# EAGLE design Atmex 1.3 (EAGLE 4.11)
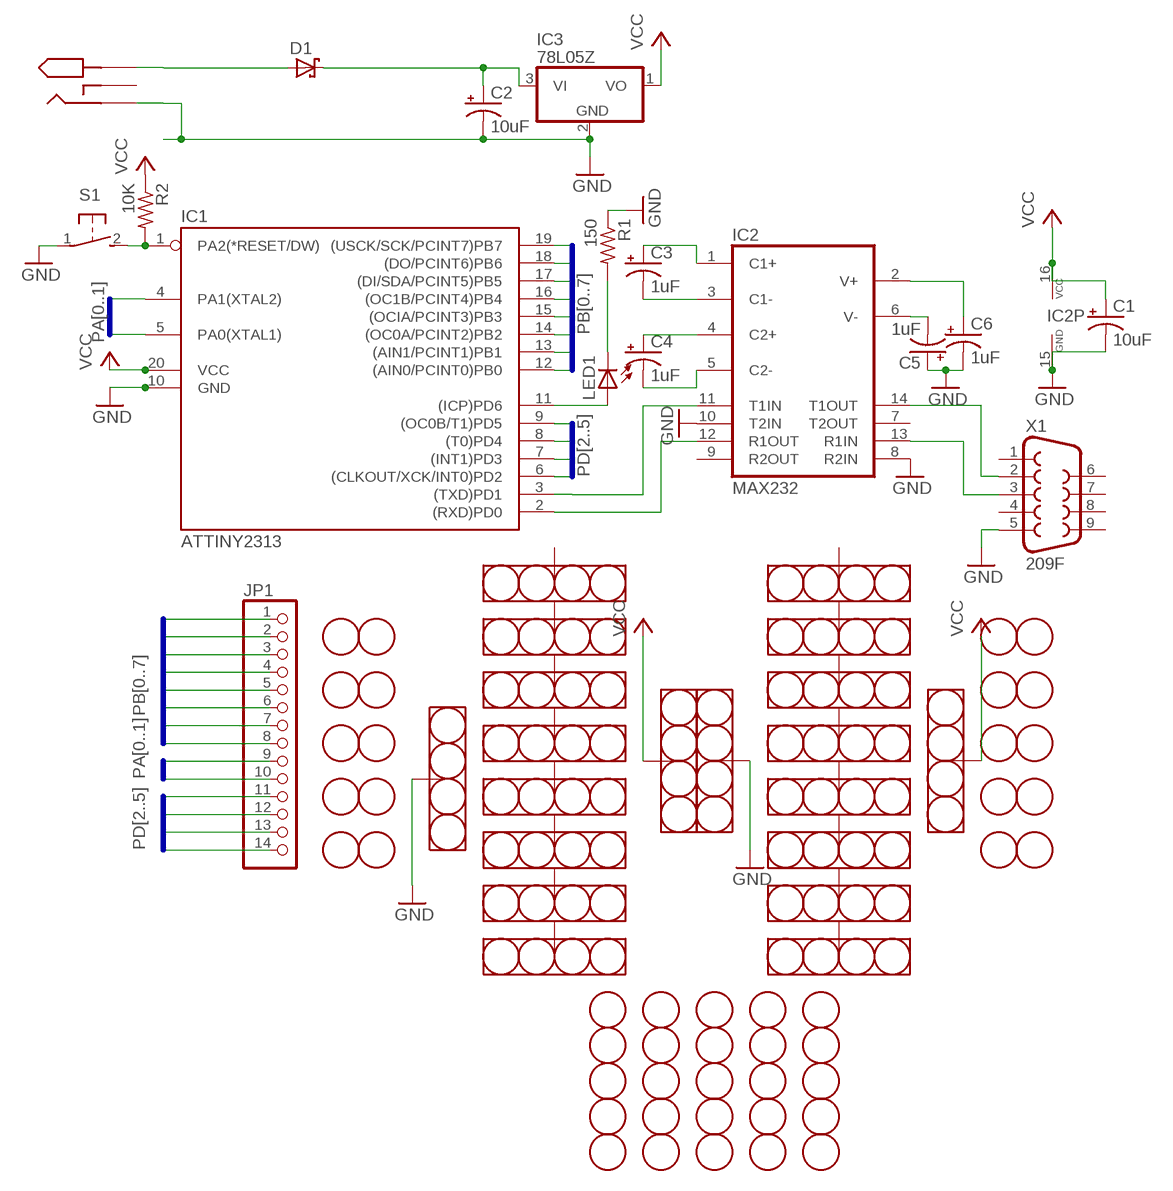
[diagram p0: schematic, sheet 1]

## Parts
C1  10uF  CPOL-USE2-5  [E2-5]
C2  10uF  CPOL-USE2-5  [E2-5]
C3  1uF  CPOL-USE1.8-4  [E1,8-4]
C4  1uF  CPOL-USE1.8-4  [E1,8-4]
C5  1uF  CPOL-USE1.8-4  [E1,8-4]
C6  1uF  CPOL-USE1.8-4  [E1,8-4]
D1  SCHOTTKY-DIODEDO35-7  [DO35-7]
IC1  ATTINY2313  [DIL20]
IC2  MAX232  [DIL16]
IC3  78L05Z  [TO92]
JP1  PINHD-1X14  [1X14]
LED1  LED5MM  [LED5MM]
R1  150  R-US_0204/7  [0204/7]
R2  10K  R-US_0204/7  [0204/7]
S1  31-XX  [B3F-31XX]
U$1  2.1MMJACK  [PJ-102A]
U$2  PROTOAREAPROTO3  PROTOAREA3  [PROTO_3]
U$3  PROTOAREAPROTO3  PROTOAREA3  [PROTO_3]
U$4  PROTOAREAPROTO3  PROTOAREA3  [PROTO_3]
U$5  PROTOAREAPROTO3  PROTOAREA3  [PROTO_3]
U$6  PROTOAREAPROTO3  PROTOAREA3  [PROTO_3]
U$7  PROTOAREAPROTO3  PROTOAREA3  [PROTO_3]
U$8  PROTOAREAPROTO3  PROTOAREA3  [PROTO_3]
U$9  PROTOAREAPROTO3  PROTOAREA3  [PROTO_3]
U$10  PROTOAREAPROTO3  PROTOAREA3  [PROTO_3]
U$11  PROTOAREAPROTO3  PROTOAREA3  [PROTO_3]
U$12  HEADER12  [HEADER_12]
U$13  HEADER12  [HEADER_12]
U$14  PROTOAREAPROTO3  PROTOAREA3  [PROTO_3]
U$15  PROTOAREAPROTO3  PROTOAREA3  [PROTO_3]
U$16  PROTOAREA  PROTOAREA12  [PROTO_12]
U$17  PROTOAREA  PROTOAREA12  [PROTO_12]
U$18  PROTOAREAPROTO3  PROTOAREA3  [PROTO_3]
U$19  PROTOAREAPROTO3  PROTOAREA3  [PROTO_3]
U$21  PROTOAREAPROTO8  PROTOAREA8  [PROTO_8]
U$22  PROTOAREAPROTO8  PROTOAREA8  [PROTO_8]
U$23  PROTOAREAPROTO3  PROTOAREA3  [PROTO_3]
U$24  PROTOAREAPROTO3  PROTOAREA3  [PROTO_3]
U$25  HEADER12  [HEADER_12]
U$26  HEADER12  [HEADER_12]
U$27  HEADER14  [HEADER_14]
U$28  HEADER8  [HEADER_8]
U$29  HEADER8  [HEADER_8]
U$30  HEADER8  [HEADER_8]
U$31  HEADER8  [HEADER_8]
X1  209F  F09D  [F09D]

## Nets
GND: C1.- C2.- C5.+ C6.- IC1.10(GND) IC2.8(R2IN) IC2.10(T2IN) IC2.15(GND) IC3.2(GND) R1.1 S1.1(P) U$1.R U$16.P$1 U$22.P$1 X1.5
N$1: C3.- IC2.3(C1-)
N$2: C3.+ IC2.1(C1+)
N$3: C4.+ IC2.4(C2+)
N$4: C4.- IC2.5(C2-)
N$5: IC1.1(PA2(*RESET/DW)) R2.2 S1.2(S)
N$6: C2.+ D1.C IC3.3(VI)
N$7: C5.- IC2.6(V-)
N$8: IC2.13(R1IN) X1.3
N$9: C6.+ IC2.2(V+)
N$10: IC2.14(T1OUT) X1.2
N$11: IC1.11((ICP)PD6) LED1.A
N$12: LED1.K(C) R1.2
N$13: D1.A U$1.T
PA0: IC1.5(PA0(XTAL1)) JP1.9
PA1: IC1.4(PA1(XTAL2)) JP1.10
PB0: IC1.12((AIN0/PCINT0)PB0) JP1.1
PB1: IC1.13((AIN1/PCINT1)PB1) JP1.2
PB2: IC1.14((OC0A/PCINT2)PB2) JP1.3
PB3: IC1.15((OCIA/PCINT3)PB3) JP1.4
PB4: IC1.16((OC1B/PCINT4)PB4) JP1.5
PB5: IC1.17((DI/SDA/PCINT5)PB5) JP1.6
PB6: IC1.18((DO/PCINT6)PB6) JP1.7
PB7: IC1.19((USCK/SCK/PCINT7)PB7) JP1.8
PD0: IC1.2((RXD)PD0) IC2.12(R1OUT)
PD1: IC1.3((TXD)PD1) IC2.11(T1IN)
PD2: IC1.6((CLKOUT/XCK/INT0)PD2) JP1.11
PD3: IC1.7((INT1)PD3) JP1.12
PD4: IC1.8((T0)PD4) JP1.13
PD5: IC1.9((OC0B/T1)PD5) JP1.14
VCC: C1.+ IC1.20(VCC) IC2.16(VCC) IC3.1(VO) R2.1 U$17.P$1 U$21.P$1
Unconnected: IC2.7(T2OUT) IC2.9(R2OUT) U$1.T_S U$2.P$1 U$3.P$1 U$4.P$1 U$5.P$1 U$6.P$1 U$7.P$1 U$8.P$1 U$9.P$1 U$10.P$1 U$11.P$1 U$14.P$1 U$15.P$1 U$18.P$1 U$19.P$1 U$23.P$1 U$24.P$1 X1.1 X1.4 X1.6 X1.7 X1.8 X1.9

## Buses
PB[0..7]
PD[2..5]
PA[0..1]

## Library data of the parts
C1-C6 = rcl:CPOL-US: POLARIZED CAPACITOR, American symbol
D1 = diode:SCHOTTKY-DIODE: Schottky Diode
IC1 = atmex:ATTINY2313
IC2 = maxim:MAX232: RS232 TRANSEIVER
IC3 = linear:78*: Positive VOLTAGE REGULATOR
JP1 = pinhead:PINHD-1X14: PIN HEADER
LED1 = led:LED: LED
R1 R2 = rcl:R-US_: RESISTOR, American symbol
S1 = switch-omron:31-XX: OMRON SWITCH
U$1 = atmex:2.1MMJACK
U$2-U$11 U$14-U$19 U$21-U$24 = atmex:PROTOAREA
U$12 U$13 U$25-U$31 = atmex:HEADER
X1 = con-subd:F09: SUB-D

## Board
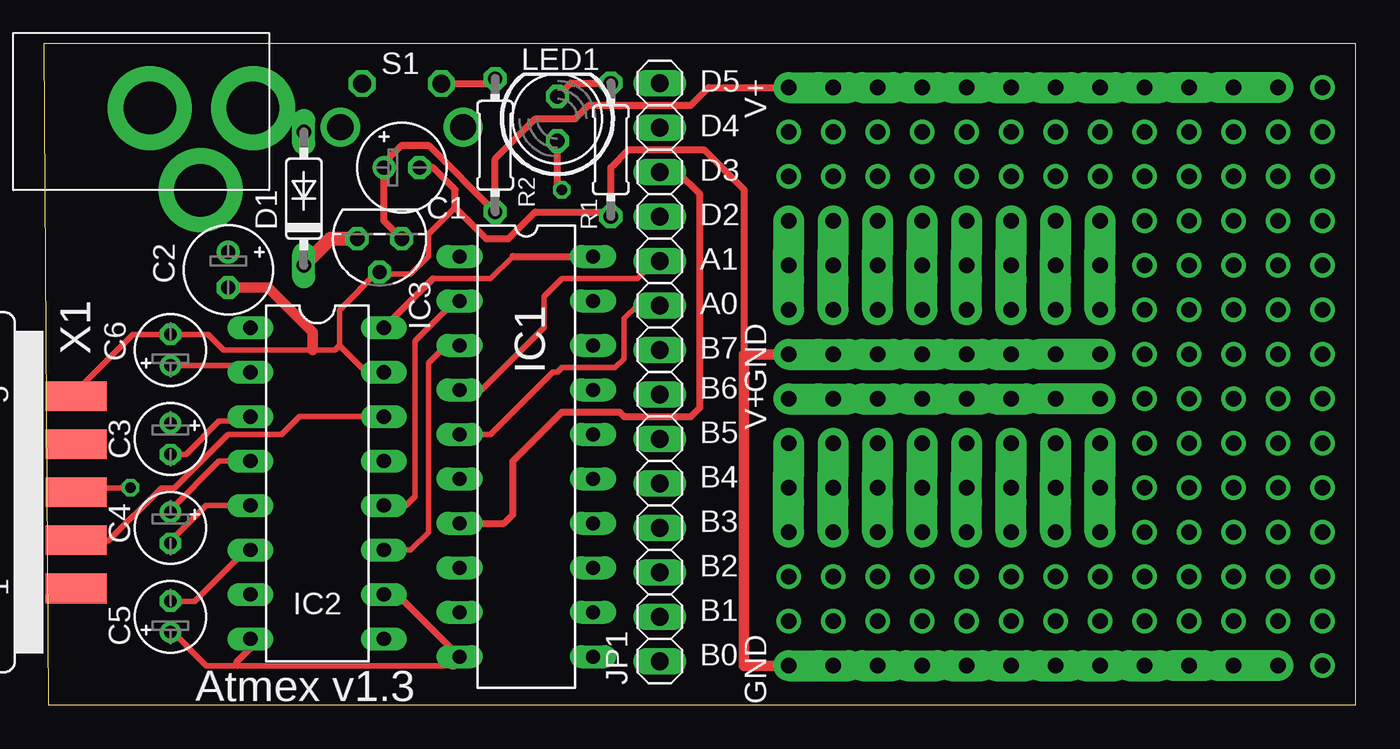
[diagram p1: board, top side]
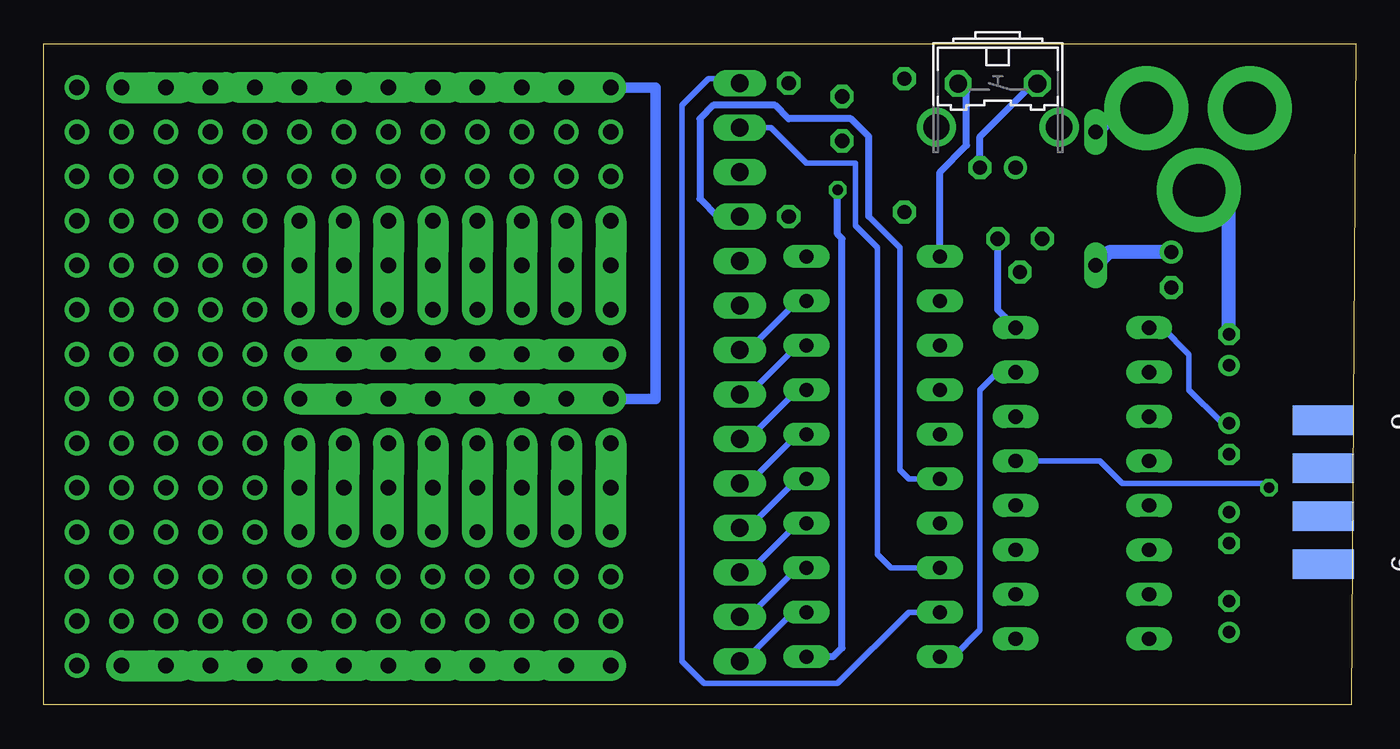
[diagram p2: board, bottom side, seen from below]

Size 74.92 x 37.77 mm. Coordinates in mm from the lower left corner, seen from the top.
Outline: 0,37.77 0.25,0 74.92,0 74.92,37.77 0,37.77
Copper layers (1*16): Top 0.035mm / dielectric 1.5mm / Bottom 0.035mm
Design rules "default": minimum track width 10mil, minimum drill 24mil, track to track 8mil, track to pad 8mil, pad to pad 8mil, via to via 8mil, smd to smd 8mil, copper to edge 40mil, drill to drill 8mil, minimum pad ring 10mil, minimum via ring 8mil, stop-mask expansion 4mil, vias tented up to drill 0mil, thermal gap 10mil

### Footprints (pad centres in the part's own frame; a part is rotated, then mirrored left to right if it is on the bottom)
E2-5 = drill 0.813 pad 1.27 round: + -1.016,0 | drill 0.813 pad 1.27 octagon: - 1.016,0
E1,8-4 = drill 0.711 pad 1.168 round: + -0.889,0 | drill 0.711 pad 1.168 octagon: - 0.889,0
DO35-7 = drill 0.813 long: A 3.81,0; C -3.81,0
DIL20 = drill 0.813 long: 1 -11.43,-3.81; 2 -8.89,-3.81; 3 -6.35,-3.81; 4 -3.81,-3.81; 5 -1.27,-3.81; 6 1.27,-3.81; 7 3.81,-3.81; 8 6.35,-3.81; 9 8.89,-3.81; 10 11.43,-3.81; 11 11.43,3.81; 12 8.89,3.81; 13 6.35,3.81; 14 3.81,3.81; 15 1.27,3.81; 16 -1.27,3.81; 17 -3.81,3.81; 18 -6.35,3.81; 19 -8.89,3.81; 20 -11.43,3.81
DIL16 = drill 0.813 long: 1 -8.89,-3.81; 2 -6.35,-3.81; 3 -3.81,-3.81; 4 -1.27,-3.81; 5 1.27,-3.81; 6 3.81,-3.81; 7 6.35,-3.81; 8 8.89,-3.81; 9 8.89,3.81; 10 6.35,3.81; 11 3.81,3.81; 12 1.27,3.81; 13 -1.27,3.81; 14 -3.81,3.81; 15 -6.35,3.81; 16 -8.89,3.81
TO92 = drill 0.813 octagon: 1 -1.27,0; 2 0,1.905; 3 1.27,0
1X14 = drill 1.016 long: 1 -16.51,0; 2 -13.97,0; 3 -11.43,0; 4 -8.89,0; 5 -6.35,0; 6 -3.81,0; 7 -1.27,0; 8 1.27,0; 9 3.81,0; 10 6.35,0; 11 8.89,0; 12 11.43,0; 13 13.97,0; 14 16.51,0
LED5MM = drill 0.813 octagon: A -1.27,0; K 1.27,0
0204/7 = drill 0.813 octagon: 1 -3.81,0; 2 3.81,0
B3F-31XX = drill 1.016 octagon: 1 -2.261,-1.245; 2 2.261,-1.245 | drill 1.499 pad 2.159 round: 3 -3.505,1.245; 4 3.505,1.245
PJ-102A = drill 3 pad 4.8 round: R -4.6,-6.29; T 0.1,-9.29; T_S 0.1,-3.39
PROTO_3 = drill 0.889 pad 1.778 offset: P$1 -2.54,0; P$3 2.54,0 | drill 0.889 pad 1.778 long: P$2 0,0
HEADER_12 = drill 0.889 round: P$1 2.54,0; P$2 0,0; P$3 -2.54,0; P$4 -5.08,0; P$5 -7.62,0; P$6 -10.16,0; P$7 5.08,0; P$8 7.62,0; P$9 10.16,0; P$10 12.7,0; P$13 -12.7,0; P$14 15.24,0
PROTO_12 = drill 0.889 pad 1.778 offset: P$1 -15.24,0; P$7 12.7,0 | drill 0.889 pad 1.778 long: P$2 0,0; P$3 -2.54,0; P$5 -5.08,0; P$6 5.08,0; P$8 7.62,0; P$9 -7.62,0; P$10 -10.16,0; P$11 -12.7,0; P$12 10.16,0; P$14 2.54,0
PROTO_8 = drill 0.889 pad 1.778 offset: P$1 -8.89,0; P$7 8.89,0 | drill 0.889 pad 1.778 long: P$2 -1.27,0; P$3 -3.81,0; P$5 -6.35,0; P$6 3.81,0; P$8 6.35,0; P$9 1.27,0
HEADER_14 = drill 0.889 round: P$1 0,0; P$2 -2.54,0; P$3 -5.08,0; P$4 -7.62,0; P$5 -10.16,0; P$6 -12.7,0; P$7 2.54,0; P$8 5.08,0; P$9 7.62,0; P$10 10.16,0; P$11 12.7,0; P$12 15.24,0; P$13 -15.24,0; P$14 17.78,0
HEADER_8 = drill 0.889 round: P$1 2.54,0; P$2 0,0; P$3 -2.54,0; P$4 -5.08,0; P$5 -7.62,0; P$6 -10.16,0; P$7 5.08,0; P$8 7.62,0
F09D = smd 1.7 x 3.5: 1 -5.486,-6.045; 2 -2.743,-6.045; 3 0,-6.045; 4 2.743,-6.045; 5 5.486,-6.045 | smd 1.7 x 3.5 bottom: 6 -4.115,-6.045; 7 -1.372,-6.045; 8 1.372,-6.045; 9 4.115,-6.045

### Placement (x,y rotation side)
C1  20.44,30.7 0 top
C2  10.54,24.85 270 top
C3  7.23,15.2 270 top
C4  7.23,10.12 270 top
C5  7.23,5.04 90 top
C6  7.23,20.28 90 top
D1  14.85,28.92 90 top
IC1  27.55,14.19 270 top
IC2  15.62,12.66 270 top
IC3  19.17,26.63 180 top
JP1  35.17,19.01 90 top
LED1  29.33,33.49 90 top
R1  32.38,31.71 90 top
R2  25.78,31.97 90 top
S1  20.44,34.25 180 bottom
U$1  2.66,34 90 top
U$2  50.16,12.41 90 bottom
U$3  45.08,25.11 90 bottom
U$4  42.54,25.11 90 bottom
U$5  42.54,12.41 90 bottom
U$6  45.08,12.41 90 bottom
U$7  47.62,12.41 90 bottom
U$8  52.7,12.41 90 bottom
U$9  55.24,12.41 90 bottom
U$10  57.78,12.41 90 bottom
U$11  60.32,12.41 90 bottom
U$12  62.86,17.49 90 bottom
U$13  65.4,17.49 90 bottom
U$14  47.62,25.11 90 bottom
U$15  50.16,25.11 90 bottom
U$16  57.78,2.25 180 bottom
U$17  57.78,35.27 180 bottom
U$18  52.7,25.11 90 bottom
U$19  55.24,25.11 90 bottom
U$21  51.43,17.49 180 bottom
U$22  51.43,20.03 180 bottom
U$23  57.78,25.11 90 bottom
U$24  60.32,25.11 90 bottom
U$25  67.94,17.49 90 bottom
U$26  70.48,17.49 90 bottom
U$27  73.02,17.49 90 bottom
U$28  52.7,4.79 180 bottom
U$29  52.7,7.33 180 bottom
U$30  52.7,30.19 180 bottom
U$31  52.7,32.73 180 bottom
X1  -4.2,12.15 90 top

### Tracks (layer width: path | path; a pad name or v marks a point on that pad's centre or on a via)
GND
  Top 0.305: IC2.15 18.41,19.01 16.89,20.54 | IC3.2 19.17,24.85 19.04,24.73 | 16.89,20.54 16.89,22.57 19.04,24.73 | 23.49,28.41 21.97,26.89 21.97,25.62 20.95,24.6 19.17,24.6 19.04,24.73 | 16.89,20.54 16.63,20.28 15.36,20.28 10.28,20.28 9.39,21.17 C6.- 5.08,21.17 1.65,17.74 1.75,17.64 X1.5 | 23.24,2.25 11.04,2.25 9.27,2.25 7.23,4.28 C5.+
  Top 0.406: C1.- 22.22,30.7 23.49,29.43 23.49,28.41 25.27,26.63 26.54,26.63 28.06,28.16 32.38,28.16 R1.1 32.38,30.7 33.4,31.71 37.71,31.71 40,29.43 40,20.03 | 11.04,2.25 11.04,2.5 11.81,3.26 IC2.8 | IC2.10 20.19,6.31 IC1.10 23.74,2.5 23.49,2.25 23.24,2.25
  Top 0.61: U$22.P$1 40,20.03 40,2.25 U$16.P$1 | S1.1 18.18,35.52 | C2.- 12.82,23.84 15.36,21.3 15.36,20.28
  Bottom 0.305: IC2.15 20.44,19.01 21.46,18 21.46,4.28 22.98,2.76
  Bottom 0.406: C1.- 21.46,32.47 18.41,35.52 18.16,35.52 S1.1 | IC1.10 22.98,2.76
  Bottom 0.813: U$1.R 7.23,29.4 C6.-
N$1
  Top 0.305: C3.- 8.12,14.31 10.03,16.22 11.55,16.22 IC2.3
N$2
  Bottom 0.305: IC2.1 11.04,21.55 9.52,20.03 9.52,18 7.74,16.22 C3.+
N$3
  Top 0.305: IC2.4 10.03,13.93 7.23,11.14 C4.+
N$4
  Top 0.305: C4.- 7.23,9.36 9.27,11.39 IC2.5
N$5
  Top 0.305: S1.2 22.96,35.5 22.98,35.52 24,35.52
  Top 0.406: S1.2 25.5,35.5 R2.2
  Bottom 0.406: IC1.1 23.74,30.44 22.22,31.97 22.22,35.01 S1.2 22.73,35.52
N$6
  Top 0.406: IC3.3 17.9,26.38 17.65,26.63
  Top 0.813: 17.65,26.63 16.38,26.63 D1.C
  Bottom 0.305: IC3.3 17.9,27.14
  Bottom 0.813: C2.+ 14.09,25.87 D1.C
N$7
  Top 0.305: IC2.6 11.81,9.11 8.63,5.93 C5.-
N$8  (via drill 0.61)
  Top 0.305: X1.3 1.85,12.36 1.9,12.41 v4.95,12.41
  Bottom 0.305: IC2.13 14.6,13.93 13.33,12.66 5.2,12.66 v4.95,12.41
N$9
  Top 0.305: C6.+ 11.43,19.39 IC2.2
N$10
  Top 0.305: IC2.14 14.6,16.47 13.58,15.46 10.54,15.46 7.49,12.41 6.73,12.41 3.68,9.36 1.9,9.36 X1.2 | X1.2
N$11  (via drill 0.61)
  Top 0.406: LED1.A 29.33,29.43 v29.59,29.43
  Bottom 0.406: v29.59,29.43 29.59,26.89 29.33,26.63 29.33,3.26 29.84,2.76 IC1.11
N$12
  Top 0.406: R1.2 30.09,35.52 LED1.K
N$13
  Bottom 0.813: U$1.T 13.43,34.1 D1.A
PA0
  Top 0.305: IC1.5 25.52,15.46 29.08,19.01 29.33,19.01 29.59,19.27 32.63,19.27 33.14,19.77 33.14,22.06 33.9,22.82 JP1.9
PA1
  Top 0.305: IC1.4 25.01,18 28.57,21.55 28.57,23.33 29.59,24.35 33.9,24.35 34.92,25.36 JP1.10
PB0
  Bottom 0.305: JP1.1 34.92,2.5 32.13,5.3 IC1.12
PB1
  Bottom 0.305: JP1.2 34.67,5.04 31.87,7.84 IC1.13
PB2
  Bottom 0.305: JP1.3 34.67,7.58 31.87,10.38 IC1.14
PB3
  Bottom 0.305: JP1.4 34.67,10.12 31.87,12.92 IC1.15
PB4
  Bottom 0.305: JP1.5 34.92,12.41 31.87,15.46 IC1.16
PB5
  Bottom 0.305: JP1.6 34.92,14.95 31.87,18 IC1.17
PB6
  Bottom 0.305: JP1.7 34.67,17.74 31.87,20.54 IC1.18
PB7
  Bottom 0.305: IC1.19 31.87,23.08 34.41,20.54 34.92,20.54 JP1.8
PD0
  Top 0.305: IC1.2 23.49,23.08 21.2,20.79 21.2,11.9 20.7,11.39 IC2.12
PD1
  Top 0.305: IC1.3 22.98,20.54 21.97,19.52 21.97,9.87 20.95,8.85 IC2.11
PD2
  Bottom 0.305: IC1.6 25.52,12.92 26.03,13.42 26.03,26.12 27.81,27.9
  Bottom 0.406: 27.81,27.9 27.81,32.47 28.82,33.49 32.38,33.49 33.14,34.25 36.7,34.25 37.46,33.49 37.46,28.92 36.44,27.9 JP1.11
PD3
  Top 0.406: IC1.7 26.28,10.38 26.79,10.88 26.79,13.93 29.59,16.73 32.89,16.73 33.14,16.47 36.95,16.47 37.46,16.98 37.46,29.17 36.19,30.44 JP1.12
PD4
  Bottom 0.305: IC1.8 26.54,7.84 27.3,8.6 27.3,26.12 28.57,27.39 28.57,30.95 31.36,30.95 33.4,32.98 JP1.13
PD5
  Bottom 0.305: IC1.9 25.52,5.3 29.59,1.23 37.21,1.23 38.48,2.5 38.48,34.25 36.95,35.78 35.43,35.78 JP1.14
VCC
  Top 0.305: 26.79,25.62 25.52,24.35 22.22,24.35
  Top 0.406: IC3.1 19.43,27.65 C1.+ 19.17,30.7 20.44,31.97 21.97,31.97 R2.1 25.78,31.2 28.06,33.49 30.35,33.49 31.11,34.25 36.95,34.25 37.97,35.27 U$17.P$1 | IC2.16 22.22,24.35 | 26.79,25.62 IC1.20
  Bottom 0.406: IC3.1 20.44,22.57 IC2.16
  Bottom 0.61: U$17.P$1 40,35.27 40,17.49 U$21.P$1

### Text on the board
tNames: V+ | D5 | D4 | D3 | D2 | A1 | A0 | GND | B7 | B6 | V+ | B5 | B4 | B3 | B2 | B1 | GND | B0 | Atmex v1.3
